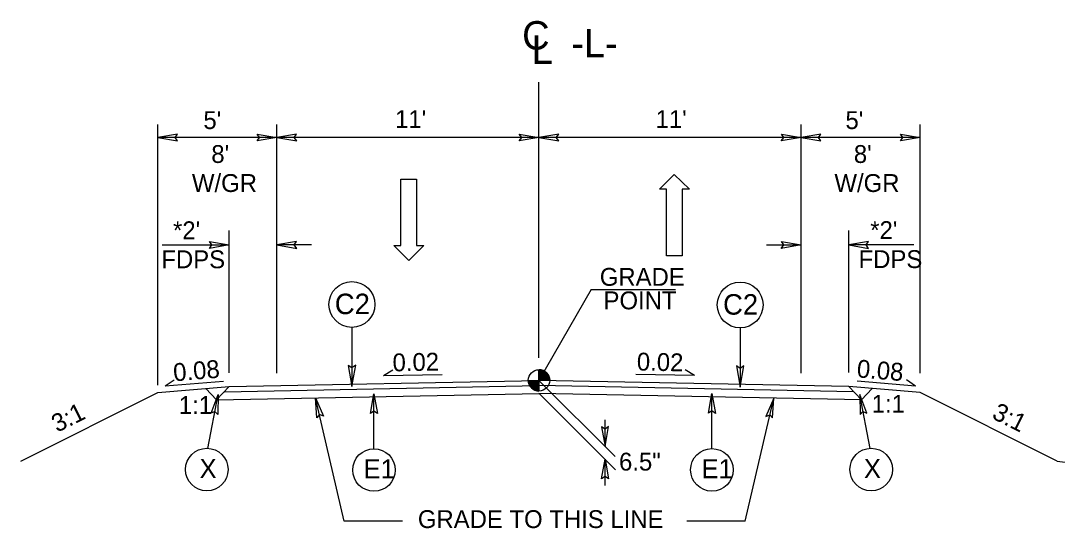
# Model space of a CAD drawing. Extents: x 60664 to 60833, y 51234 to 51344.
# Drawn here: x 60735.82 to 60779.32, y 51285.14 to 51306.46 of the extents above; entities that cross this region are included whole.
import ezdxf

# ---------------------------------------------------------------- set-up
doc = ezdxf.new("R2010")
doc.units = 0
for name, color, linetype in [('Prop Dimension', 7, 'Continuous'), ('Prop Dimension Text', 7, 'Continuous'), ('Prop Lane Arrow CELL', 7, 'Continuous'), ('Typical Grade Point Symbol CELL', 7, 'Continuous'), ('Typical ID Circle CELL', 7, 'Continuous'), ('Typical Pavement Slope CELL', 7, 'Continuous'), ('Typical Pavement Slope Information CELL', 7, 'Continuous'), ('Typical Shoulder Slope CELL', 7, 'Continuous'), ('Typical Shoulder Slope Information CELL', 7, 'Continuous'), ('Typical Slope Point Local CELL', 7, 'Continuous'), ('Typical Terminator CELL', 7, 'Continuous'), ('Typical Text General CELL', 7, 'Continuous'), ('Typical Text Grade Point CELL', 7, 'Continuous'), ('Typical Text ID Circle CELL', 7, 'Continuous')]:
    doc.layers.add(name, color=color, linetype=linetype)

msp = doc.modelspace()

# ---------------------------------------------------------------- linework, layer by layer
at = {"layer": 'Prop Dimension'}
for p, q in [((60757.572, 51292.299), (60757.572, 51303.881)), ((60746.572, 51291.651), (60746.572, 51302.1)), ((60768.572, 51291.652), (60768.572, 51302.1)), ((60746.572, 51301.56), (60741.572, 51301.56)), ((60757.572, 51301.56), (60746.572, 51301.56)), ((60768.572, 51301.56), (60757.572, 51301.56)), ((60773.572, 51301.56), (60768.572, 51301.56)), ((60744.572, 51291.672), (60744.572, 51297.654)), ((60770.572, 51291.691), (60770.572, 51297.654)), ((60741.755, 51297.044), (60744.572, 51297.044)), ((60748.03, 51297.044), (60746.572, 51297.044)), ((60767.114, 51297.044), (60768.572, 51297.044)), ((60773.298, 51297.044), (60770.572, 51297.044)), ((60749.397, 51285.447), (60748.195, 51290.622)), ((60766.222, 51285.438), (60767.424, 51290.613)), ((60760.343, 51288.58), (60760.343, 51289.69)), ((60760.343, 51286.935), (60760.343, 51288.045)), ((60751.849, 51285.447), (60749.397, 51285.447)), ((60766.222, 51285.438), (60763.771, 51285.438))]:
    msp.add_line(p, q, dxfattribs=at)
at = {"layer": 'Prop Dimension Text'}
for p, q in [((60741.572, 51291.151), (60741.572, 51302.1)), ((60773.572, 51291.652), (60773.572, 51302.1)), ((60757.572, 51291.351), (60760.768, 51288.156)), ((60757.579, 51290.81), (60760.787, 51287.602))]:
    msp.add_line(p, q, dxfattribs=at)
at = {"layer": 'Prop Lane Arrow CELL'}
for p, q in [((60762.628, 51299.38), (60763.246, 51300.008)), ((60763.246, 51300.008), (60763.885, 51299.38)), ((60751.776, 51297.017), (60751.776, 51299.809)), ((60751.776, 51299.809), (60752.434, 51299.809)), ((60752.434, 51299.809), (60752.434, 51297.017)), ((60762.927, 51299.38), (60762.628, 51299.38)), ((60762.927, 51296.588), (60762.927, 51299.38)), ((60763.885, 51299.38), (60763.585, 51299.38)), ((60763.585, 51299.38), (60763.585, 51296.588)), ((60752.115, 51296.388), (60751.477, 51297.017)), ((60751.477, 51297.017), (60751.776, 51297.017)), ((60752.734, 51297.017), (60752.115, 51296.388)), ((60752.434, 51297.017), (60752.734, 51297.017)), ((60763.585, 51296.588), (60762.927, 51296.588))]:
    msp.add_line(p, q, dxfattribs=at)
at = {"layer": 'Typical Grade Point Symbol CELL'}
for p, q in [((60757.572, 51291.351), (60757.572, 51291.799)), ((60757.124, 51291.351), (60757.572, 51291.351)), ((60757.571, 51290.904), (60757.572, 51291.351)), ((60757.572, 51291.351), (60757.571, 51290.904)), ((60758.02, 51291.351), (60757.572, 51291.351))]:
    msp.add_line(p, q, dxfattribs=at)
for points in [[(60757.576, 51291.799), (60757.576, 51291.799), (60757.576, 51291.351)], [(60757.585, 51291.799), (60757.585, 51291.351)], [(60757.594, 51291.798), (60757.594, 51291.351)], [(60757.603, 51291.798), (60757.603, 51291.351)], [(60757.612, 51291.797), (60757.612, 51291.351)], [(60757.621, 51291.796), (60757.621, 51291.351)], [(60757.63, 51291.795), (60757.63, 51291.351)], [(60757.639, 51291.794), (60757.639, 51291.351)], [(60757.648, 51291.793), (60757.648, 51291.351)], [(60757.657, 51291.791), (60757.657, 51291.351)], [(60757.666, 51291.789), (60757.666, 51291.351)], [(60757.675, 51291.787), (60757.675, 51291.351)], [(60757.683, 51291.785), (60757.683, 51291.351)], [(60757.692, 51291.782), (60757.692, 51291.351)], [(60757.701, 51291.78), (60757.701, 51291.351)], [(60757.71, 51291.777), (60757.71, 51291.351)], [(60757.719, 51291.774), (60757.719, 51291.351)], [(60757.728, 51291.771), (60757.728, 51291.351)], [(60757.737, 51291.767), (60757.737, 51291.351)], [(60757.746, 51291.763), (60757.746, 51291.351)], [(60757.755, 51291.759), (60757.755, 51291.351)], [(60757.764, 51291.755), (60757.764, 51291.351)], [(60757.773, 51291.751), (60757.773, 51291.351)], [(60757.782, 51291.746), (60757.782, 51291.351)], [(60757.791, 51291.741), (60757.791, 51291.351)], [(60757.8, 51291.736), (60757.8, 51291.351)], [(60757.809, 51291.731), (60757.809, 51291.351)], [(60757.818, 51291.725), (60757.818, 51291.351)], [(60757.827, 51291.719), (60757.827, 51291.351)], [(60757.836, 51291.712), (60757.836, 51291.351)], [(60757.845, 51291.706), (60757.845, 51291.351)], [(60757.854, 51291.7), (60757.854, 51291.351)], [(60757.863, 51291.692), (60757.863, 51291.351)], [(60757.871, 51291.684), (60757.871, 51291.351)], [(60757.88, 51291.676), (60757.88, 51291.351)], [(60757.889, 51291.667), (60757.889, 51291.351)], [(60757.898, 51291.658), (60757.898, 51291.351)], [(60757.126, 51291.351), (60757.126, 51291.303)], [(60757.135, 51291.351), (60757.135, 51291.25)], [(60757.144, 51291.351), (60757.144, 51291.218)], [(60757.153, 51291.351), (60757.153, 51291.191)], [(60757.162, 51291.351), (60757.162, 51291.17)], [(60757.171, 51291.351), (60757.171, 51291.151)], [(60757.18, 51291.351), (60757.18, 51291.135)], [(60757.189, 51291.351), (60757.189, 51291.119)], [(60757.198, 51291.351), (60757.198, 51291.105)], [(60757.207, 51291.351), (60757.207, 51291.092)], [(60757.216, 51291.351), (60757.216, 51291.08)], [(60757.225, 51291.351), (60757.225, 51291.069)], [(60757.234, 51291.351), (60757.234, 51291.058)], [(60757.243, 51291.351), (60757.243, 51291.048)], [(60757.252, 51291.351), (60757.252, 51291.038)], [(60757.261, 51291.351), (60757.261, 51291.029)], [(60757.27, 51291.351), (60757.27, 51291.021)], [(60757.279, 51291.351), (60757.279, 51291.013)], [(60757.288, 51291.351), (60757.288, 51291.005)], [(60757.297, 51291.351), (60757.297, 51290.998)], [(60757.306, 51291.351), (60757.306, 51290.991)], [(60757.314, 51291.351), (60757.314, 51290.985)], [(60757.323, 51291.351), (60757.323, 51290.979)], [(60757.332, 51291.351), (60757.332, 51290.973)], [(60757.341, 51291.351), (60757.341, 51290.968)], [(60757.35, 51291.351), (60757.35, 51290.963)], [(60757.359, 51291.351), (60757.359, 51290.958)], [(60757.368, 51291.351), (60757.368, 51290.953)], [(60757.377, 51291.351), (60757.377, 51290.949)], [(60757.386, 51291.351), (60757.386, 51290.945)], [(60757.395, 51291.351), (60757.395, 51290.941)], [(60757.404, 51291.351), (60757.404, 51290.937)], [(60757.413, 51291.351), (60757.413, 51290.933)], [(60757.422, 51291.351), (60757.422, 51290.93)], [(60757.431, 51291.351), (60757.431, 51290.927)], [(60757.44, 51291.351), (60757.44, 51290.924)], [(60757.449, 51291.351), (60757.449, 51290.922)], [(60757.458, 51291.351), (60757.458, 51290.919)], [(60757.467, 51291.351), (60757.467, 51290.917)], [(60757.476, 51291.351), (60757.476, 51290.915)], [(60757.485, 51291.351), (60757.485, 51290.913)], [(60757.493, 51291.351), (60757.493, 51290.911)], [(60757.502, 51291.351), (60757.502, 51290.91)], [(60757.511, 51291.351), (60757.511, 51290.908)], [(60757.52, 51291.351), (60757.52, 51290.907)], [(60757.529, 51291.351), (60757.529, 51290.906)], [(60757.538, 51291.351), (60757.538, 51290.905)], [(60757.547, 51291.351), (60757.547, 51290.905)], [(60757.556, 51291.351), (60757.556, 51290.904)], [(60757.565, 51291.351), (60757.565, 51290.904), (60757.565, 51290.904)], [(60757.907, 51291.648), (60757.907, 51291.351)], [(60757.916, 51291.637), (60757.916, 51291.351)], [(60757.925, 51291.626), (60757.925, 51291.351)], [(60757.934, 51291.614), (60757.934, 51291.351)], [(60757.943, 51291.601), (60757.943, 51291.351)], [(60757.952, 51291.587), (60757.952, 51291.351)], [(60757.961, 51291.572), (60757.961, 51291.351)], [(60757.97, 51291.556), (60757.97, 51291.351)], [(60757.979, 51291.537), (60757.979, 51291.351)], [(60757.988, 51291.517), (60757.988, 51291.351)], [(60757.997, 51291.492), (60757.997, 51291.351)], [(60758.006, 51291.461), (60758.006, 51291.351)], [(60758.015, 51291.415), (60758.015, 51291.351)]]:
    msp.add_lwpolyline(points, dxfattribs=at)
msp.add_circle((60757.572, 51291.352), 0.448, dxfattribs=at)
for start, end in [(359.9905, 89.9905), (179.9905, 269.9905)]:
    msp.add_arc((60757.572, 51291.352), 0.448, start, end, dxfattribs=at)
at = {"layer": 'Typical ID Circle CELL'}
for p, q in [((60749.72, 51293.581), (60749.72, 51291.096)), ((60766.015, 51293.561), (60766.015, 51291.076))]:
    msp.add_line(p, q, dxfattribs=at)
for centre in [(60749.72, 51294.543), (60766.015, 51294.523)]:
    msp.add_circle(centre, 0.962, dxfattribs=at)
at = {"layer": 'Typical Pavement Slope CELL'}
for p, q in [((60744.572, 51291.091), (60757.572, 51291.351)), ((60770.572, 51291.091), (60757.572, 51291.351)), ((60744.042, 51290.539), (60757.579, 51290.81)), ((60744.368, 51290.879), (60757.572, 51291.143)), ((60771.102, 51290.539), (60757.565, 51290.81)), ((60770.776, 51290.879), (60757.572, 51291.143))]:
    msp.add_line(p, q, dxfattribs=at)
at = {"layer": 'Typical Pavement Slope Information CELL'}
for p, q in [((60751.045, 51291.557), (60751.436, 51291.793)), ((60764.099, 51291.557), (60763.708, 51291.793)), ((60741.885, 51291.12), (60742.26, 51291.381)), ((60741.885, 51291.12), (60744.334, 51291.324)), ((60751.045, 51291.557), (60753.502, 51291.606)), ((60764.099, 51291.557), (60761.642, 51291.606)), ((60773.37, 51291.117), (60770.92, 51291.321)), ((60773.37, 51291.117), (60772.994, 51291.378))]:
    msp.add_line(p, q, dxfattribs=at)
at = {"layer": 'Typical Shoulder Slope CELL'}
for p, q in [((60741.572, 51290.841), (60744.572, 51291.091)), ((60744.042, 51290.539), (60743.591, 51291.009)), ((60744.042, 51290.539), (60744.572, 51291.091)), ((60770.572, 51291.091), (60771.102, 51290.539)), ((60773.572, 51290.841), (60770.572, 51291.091)), ((60771.553, 51291.009), (60771.102, 51290.539))]:
    msp.add_line(p, q, dxfattribs=at)
at = {"layer": 'Typical Slope Point Local CELL'}
for p, q in [((60735.821, 51287.965), (60741.572, 51290.841)), ((60779.323, 51287.965), (60773.572, 51290.841))]:
    msp.add_line(p, q, dxfattribs=at)
msp.add_lwpolyline([(60779.323, 51287.965), (60780.817, 51287.779), (60781.191, 51287.779), (60781.751, 51287.779), (60782.125, 51287.779), (60782.39, 51287.911)], dxfattribs=at)
at = {"layer": 'Typical Terminator CELL'}
for points in [[(60742.4, 51301.702), (60741.572, 51301.56), (60742.405, 51301.412), (60742.299, 51301.56)], [(60745.744, 51301.702), (60746.572, 51301.56), (60745.739, 51301.412), (60745.845, 51301.56)], [(60747.4, 51301.702), (60746.572, 51301.56), (60747.405, 51301.412), (60747.299, 51301.56)], [(60756.744, 51301.702), (60757.572, 51301.56), (60756.739, 51301.412), (60756.845, 51301.56)], [(60758.4, 51301.702), (60757.572, 51301.56), (60758.405, 51301.412), (60758.299, 51301.56)], [(60767.744, 51301.702), (60768.572, 51301.56), (60767.739, 51301.412), (60767.845, 51301.56)], [(60769.4, 51301.702), (60768.572, 51301.56), (60769.405, 51301.412), (60769.299, 51301.56)], [(60772.744, 51301.702), (60773.572, 51301.56), (60772.739, 51301.412), (60772.845, 51301.56)], [(60743.744, 51297.187), (60744.572, 51297.044), (60743.739, 51296.897), (60743.845, 51297.044)], [(60747.4, 51297.187), (60746.572, 51297.044), (60747.405, 51296.897), (60747.299, 51297.044)], [(60767.744, 51297.187), (60768.572, 51297.044), (60767.739, 51296.897), (60767.845, 51297.044)], [(60771.4, 51297.187), (60770.572, 51297.044), (60771.405, 51296.897), (60771.299, 51297.044)], [(60749.567, 51291.986), (60749.72, 51291.096), (60749.879, 51291.991), (60749.72, 51291.878)], [(60765.862, 51291.966), (60766.015, 51291.076), (60766.174, 51291.971), (60766.015, 51291.857)], [(60748.244, 51289.783), (60748.195, 51290.622), (60748.527, 51289.844), (60748.36, 51289.914)], [(60767.376, 51289.774), (60767.424, 51290.613), (60767.092, 51289.835), (60767.26, 51289.905)], [(60760.201, 51289.408), (60760.343, 51288.58), (60760.491, 51289.413), (60760.343, 51289.307)], [(60760.201, 51287.217), (60760.343, 51288.045), (60760.491, 51287.213), (60760.343, 51287.318)]]:
    msp.add_lwpolyline(points, close=True, dxfattribs=at)
at = {"layer": 'Typical Text Grade Point CELL'}
for q in [(60757.572, 51291.351), (60763.297, 51295.172)]:
    msp.add_line((60759.759, 51295.172), q, dxfattribs=at)
at = {"layer": 'Typical Text ID Circle CELL'}
for p, q in [((60750.646, 51288.482), (60750.646, 51290.793)), ((60764.831, 51288.49), (60764.831, 51290.801)), ((60743.676, 51288.499), (60744.111, 51290.766)), ((60771.469, 51288.499), (60771.033, 51290.766))]:
    msp.add_line(p, q, dxfattribs=at)
for points in [[(60750.504, 51289.965), (60750.646, 51290.793), (60750.793, 51289.961), (60750.646, 51290.067)], [(60750.504, 51289.965), (60750.646, 51290.793), (60750.793, 51289.961), (60750.646, 51290.067)], [(60764.689, 51289.973), (60764.831, 51290.801), (60764.978, 51289.968), (60764.831, 51290.074)], [(60764.689, 51289.973), (60764.831, 51290.801), (60764.978, 51289.968), (60764.831, 51290.074)], [(60743.815, 51289.98), (60744.111, 51290.766), (60744.099, 51289.921), (60743.974, 51290.052)], [(60743.815, 51289.98), (60744.111, 51290.766), (60744.099, 51289.921), (60743.974, 51290.052)], [(60771.329, 51289.98), (60771.033, 51290.766), (60771.045, 51289.921), (60771.17, 51290.052)], [(60771.329, 51289.98), (60771.033, 51290.766), (60771.045, 51289.921), (60771.17, 51290.052)]]:
    msp.add_lwpolyline(points, close=True, dxfattribs=at)
for centre in [(60743.629, 51287.606), (60750.646, 51287.588), (60764.831, 51287.595), (60771.515, 51287.606)]:
    msp.add_circle(centre, 0.894, dxfattribs=at)

# ---------------------------------------------------------------- texts
at = {"layer": 'Prop Dimension Text'}
for s, height, p in [('C    ', 1.1936, (60756.864, 51305.252)), ('-L-', 1.1936, (60758.926, 51304.926)), ('L', 1.194, (60757.264, 51304.65)), ("5'", 0.75, (60743.487, 51301.911)), ("11'", 0.75, (60751.532, 51301.955)), ("11'", 0.75, (60762.465, 51301.955)), ("5'", 0.75, (60770.434, 51301.911)), ("8'", 0.75, (60743.82, 51300.488)), ("8'", 0.75, (60770.786, 51300.488)), ('W/GR', 0.75, (60743.006, 51299.269)), ('W/GR', 0.75, (60769.972, 51299.269)), ("*2'", 0.75, (60742.213, 51297.284)), ("*2'", 0.75, (60771.474, 51297.292)), ('FDPS', 0.75, (60741.723, 51296.066)), ('FDPS', 0.75, (60770.985, 51296.073)), ('1:1', 0.75, (60742.455, 51289.945)), ('1:1', 0.75, (60771.535, 51289.996)), ('6.5"', 0.75, (60760.931, 51287.566))]:
    msp.add_text(s, height=height, dxfattribs=at).set_placement(p)
at = {"layer": 'Typical Pavement Slope Information CELL'}
for rotation, p in [(1.1457, (60751.433, 51291.73)), (358.8543, (60761.673, 51291.771))]:
    msp.add_text('0.02', height=0.75, rotation=rotation, dxfattribs=at).set_placement(p)
at = {"layer": 'Typical Shoulder Slope Information CELL'}
for rotation, p in [(4.7615, (60742.252, 51291.311)), (355.2385, (60770.89, 51291.484))]:
    msp.add_text('0.08', height=0.75, rotation=rotation, dxfattribs=at).set_placement(p)
at = {"layer": 'Typical Slope Point Local CELL'}
for rotation, p in [(26.5651, (60737.101, 51289.025)), (333.4349, (60776.288, 51289.902))]:
    msp.add_text(' 3:1 ', height=0.75, rotation=rotation, dxfattribs=at).set_placement(p)
at = {"layer": 'Typical Text General CELL'}
msp.add_text('GRADE TO THIS LINE', height=0.75, dxfattribs=at).set_placement((60752.488, 51285.151))
at = {"layer": 'Typical Text Grade Point CELL'}
for s, p in [('GRADE', (60760.123, 51295.328)), ('POINT', (60760.28, 51294.34))]:
    msp.add_text(s, height=0.75, dxfattribs=at).set_placement(p)
at = {"layer": 'Typical Text ID Circle CELL'}
for s, height, p in [('C2', 0.8608, (60749.003, 51294.136)), ('C2', 0.8608, (60765.298, 51294.116)), ('X', 0.8, (60743.327, 51287.252)), ('E1', 0.8004, (60750.209, 51287.235)), ('E1', 0.8004, (60764.394, 51287.242)), ('X', 0.8, (60771.208, 51287.252))]:
    msp.add_text(s, height=height, dxfattribs=at).set_placement(p)

doc.saveas('drawing.dxf')
